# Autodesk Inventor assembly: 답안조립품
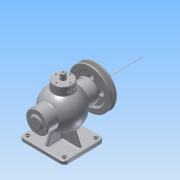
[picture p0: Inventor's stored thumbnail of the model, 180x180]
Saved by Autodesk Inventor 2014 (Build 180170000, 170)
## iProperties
Created: 2017-01
Part Number: 답안조립품
Document SubType Name: Assembly
Designer: ksu
Author: ksu
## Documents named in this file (19)
- C:\Users\ksu\Desktop\470118V1014\답안조립품.iam
- C:\Users\ksu\Desktop\470118V1014\1본체.ipt
- C:\Users\ksu\Desktop\470118V1014\V-벨트풀리.ipt
- C:\Users\ksu\Desktop\470118V1014\너트 M8.ipt
- C:\Users\ksu\Desktop\470118V1014\뒤커버.ipt
- C:\Users\ksu\Desktop\470118V1014\멈춤링- 15 x 1.ipt
- C:\Users\ksu\Desktop\470118V1014\멈춤링- 35x1.6.ipt
- KS B 1336 - 35x1.6.ipt
- C:\Users\ksu\Desktop\470118V1014\베어링- 6202.ipt
- KS B 2023 - 6202 - 15 x 35 x 11 - 7.8.ipt
- C:\Users\ksu\Desktop\470118V1014\볼트 M4 x 12.ipt
- C:\Users\ksu\Desktop\470118V1014\볼트 M4 x 16.ipt
- C:\Users\ksu\Desktop\470118V1014\부시.ipt
- C:\Users\ksu\Desktop\470118V1014\상부커버.ipt
- C:\Users\ksu\Desktop\470118V1014\슬라이드.ipt
- C:\Users\ksu\Desktop\470118V1014\앞커버.ipt
- C:\Users\ksu\Desktop\470118V1014\오일실 15 30 7.ipt
- C:\Users\ksu\Desktop\470118V1014\키 4 x 4 x 12.ipt
- C:\Users\ksu\Desktop\470118V1014\편심축.ipt
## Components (17 placed, 6 different names)
1. 1본체:1 — Mate:11, Mate:13, Mate:14, Mate:15, Mate:16, Mate:17, Mate:20, Mate:25, Mate:27
2. V-벨트풀리:1 — Mate:2, Mate:3, Flush:1
3. KS B 1336 - 35x1.6:1 — Mate:4, Mate:7
4. KS B 2023 - 6202 - 15 x 35 x 11 - 7.8:1 — Insert:3, Insert:10
5. KS B 2023 - 6202 - 15 x 35 x 11 - 7.8:2 — Mate:4, Mate:5, Mate:6, Mate:7, Mate:8, Mate:10
6. ISO 4762 M4 x 16:2 — Insert:7
7. ISO 4762 M4 x 16:3
8. ISO 4762 M4 x 16:4
9. ISO 4762 M4 x 16:5
10. ISO 4762 M4 x 16:1 — Insert:9, Mate:25
11. ISO 4762 M4 x 16:6
12. ISO 4762 M4 x 16:7
13. ISO 4762 M4 x 16:8
14. KS B 1021 - 에 따름 ISO 1207 - 미터 A  M 4 x 12:1 — Insert:11
15. KS B 1021 - 에 따름 ISO 1207 - 미터 A  M 4 x 12:2
16. KS B 1021 - 에 따름 ISO 1207 - 미터 A  M 4 x 12:3
17. KS B 1021 - 에 따름 ISO 1207 - 미터 A  M 4 x 12:4
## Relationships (23: Mate 17, Insert 5, Flush 1)
- Mate:2: V-벨트풀리:1
- Mate:3: V-벨트풀리:1
- Flush:1: V-벨트풀리:1
- Insert:3: KS B 2023 - 6202 - 15 x 35 x 11 - 7.8:1
- Mate:4: KS B 1336 - 35x1.6:1 ↔ KS B 2023 - 6202 - 15 x 35 x 11 - 7.8:2
- Mate:5: KS B 2023 - 6202 - 15 x 35 x 11 - 7.8:2
- Mate:6: KS B 2023 - 6202 - 15 x 35 x 11 - 7.8:2
- Mate:7: KS B 1336 - 35x1.6:1 ↔ KS B 2023 - 6202 - 15 x 35 x 11 - 7.8:2
- Mate:8: KS B 2023 - 6202 - 15 x 35 x 11 - 7.8:2
- Mate:10: KS B 2023 - 6202 - 15 x 35 x 11 - 7.8:2
- Mate:11: 1본체:1
- Mate:13: 1본체:1
- Mate:14: 1본체:1
- Mate:15: 1본체:1
- Mate:16: 1본체:1
- Mate:17: 1본체:1
- Insert:7: ISO 4762 M4 x 16:2
- Mate:20: 1본체:1
- Insert:9: ISO 4762 M4 x 16:1
- Insert:10: KS B 2023 - 6202 - 15 x 35 x 11 - 7.8:1
- Mate:25: 1본체:1 ↔ ISO 4762 M4 x 16:1
- Insert:11: KS B 1021 - 에 따름 ISO 1207 - 미터 A  M 4 x 12:1
- Mate:27: 1본체:1
